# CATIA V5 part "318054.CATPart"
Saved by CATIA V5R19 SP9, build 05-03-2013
Part number: 318054
Source: Unknown
Bounding box of the stored display mesh (mm): x -107.69 to 242.5, y -243 to -193.848, z 495.8 to 596.5
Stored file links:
  D:\16-SIL\kale oto\R19_V2\318054.CATPart
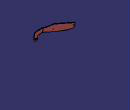
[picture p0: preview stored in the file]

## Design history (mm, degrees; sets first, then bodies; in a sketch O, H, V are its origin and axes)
Body1 "157\\124\\MANIFOLD_SOLID_BREP #74638" (main body)
  Solid1: solid without history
